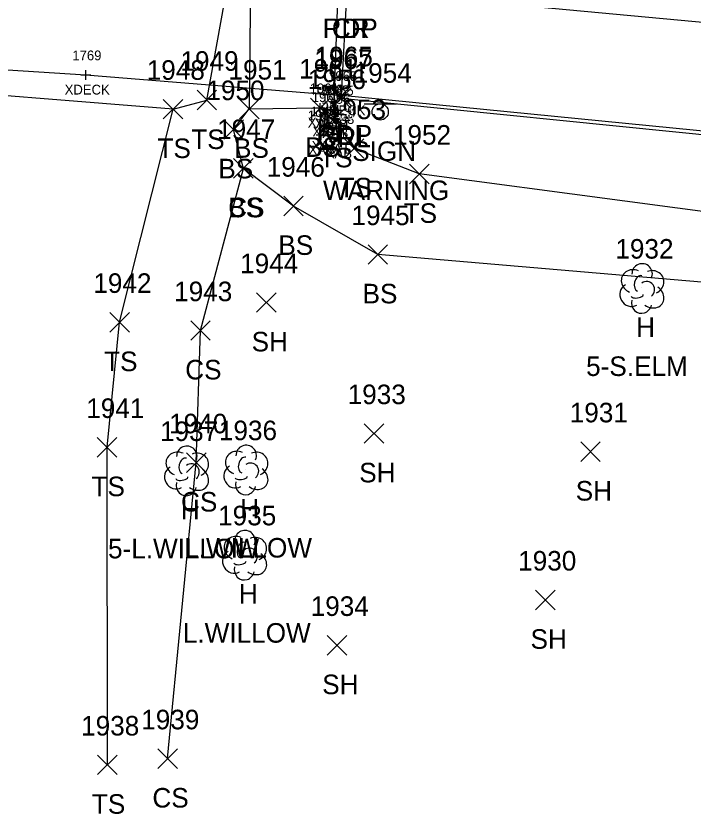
# Model space of a CAD drawing. Extents: x 1497084 to 1499861, y 734741 to 735567.
# Drawn here: x 1499561.5 to 1499630.8, y 735374.5 to 735456.1 of the extents above; entities that cross this region are included whole.
import ezdxf

# ---------------------------------------------------------------- set-up
doc = ezdxf.new("R2010")
doc.units = 0
for name, color, linetype in [('B_A', 7, 'Continuous'), ('B_I', 7, 'Continuous'), ('B_TIC', 7, 'Continuous'), ('BELB', 7, 'Continuous'), ('BSUBM', 7, 'Continuous'), ('L_A', 7, 'Continuous'), ('L_C', 7, 'Continuous'), ('L_I', 7, 'Continuous'), ('L_TIC', 7, 'Continuous'), ('LELB', 7, 'Continuous'), ('LTD', 7, 'Continuous'), ('P_A', 7, 'Continuous'), ('P_I', 7, 'Continuous'), ('P_TIC', 7, 'Continuous'), ('PET', 7, 'Continuous'), ('PRC', 7, 'Continuous'), ('R_A', 7, 'Continuous'), ('R_I', 7, 'Continuous'), ('R_TIC', 7, 'Continuous'), ('RGR', 7, 'Continuous'), ('S_A', 7, 'Continuous'), ('S_C', 7, 'Continuous'), ('S_I', 7, 'Continuous'), ('SSGN', 7, 'Continuous')]:
    doc.layers.add(name, color=color, linetype=linetype)

msp = doc.modelspace()

# ---------------------------------------------------------------- linework, layer by layer
at = {"layer": 'B_TIC'}
for p, q in [((1499568.694, 735450.037), (1499568.77, 735450.037)), ((1499594.852, 735447.923), (1499594.928, 735447.923)), ((1499592.69, 735446.665), (1499592.766, 735446.665)), ((1499593.42, 735446.544), (1499593.495, 735446.544)), ((1499593.42, 735446.544), (1499593.495, 735446.544)), ((1499594.057, 735446.482), (1499594.133, 735446.482)), ((1499594.478, 735446.445), (1499594.553, 735446.445)), ((1499594.478, 735446.445), (1499594.553, 735446.445)), ((1499593.182, 735445.765), (1499593.258, 735445.765)), ((1499594.16, 735445.59), (1499594.236, 735445.59)), ((1499594.16, 735445.59), (1499594.236, 735445.59)), ((1499592.764, 735443.901), (1499592.839, 735443.901)), ((1499593.093, 735444.295), (1499593.169, 735444.295)), ((1499594.415, 735443.992), (1499594.49, 735443.992)), ((1499594.536, 735443.527), (1499594.611, 735443.527))]:
    msp.add_line(p, q, dxfattribs=at)
for points in [[(1499568.691, 735449.537), (1499568.691, 735450.537)], [(1499568.191, 735450.037), (1499569.191, 735450.037)], [(1499594.349, 735447.923), (1499595.349, 735447.923)], [(1499594.849, 735447.423), (1499594.849, 735448.423)], [(1499592.687, 735446.165), (1499592.687, 735447.165)], [(1499593.416, 735446.044), (1499593.416, 735447.044)], [(1499593.416, 735446.044), (1499593.416, 735447.044)], [(1499594.054, 735445.982), (1499594.054, 735446.982)], [(1499592.187, 735446.665), (1499593.187, 735446.665)], [(1499592.916, 735446.544), (1499593.916, 735446.544)], [(1499592.916, 735446.544), (1499593.916, 735446.544)], [(1499593.179, 735445.265), (1499593.179, 735446.265)], [(1499593.554, 735446.482), (1499594.554, 735446.482)], [(1499593.974, 735446.445), (1499594.974, 735446.445)], [(1499593.974, 735446.445), (1499594.974, 735446.445)], [(1499594.474, 735445.945), (1499594.474, 735446.945)], [(1499594.474, 735445.945), (1499594.474, 735446.945)], [(1499592.679, 735445.765), (1499593.679, 735445.765)], [(1499593.657, 735445.59), (1499594.657, 735445.59)], [(1499593.657, 735445.59), (1499594.657, 735445.59)], [(1499594.157, 735445.09), (1499594.157, 735446.09)], [(1499594.157, 735445.09), (1499594.157, 735446.09)], [(1499593.09, 735443.795), (1499593.09, 735444.795)], [(1499592.26, 735443.901), (1499593.26, 735443.901)], [(1499592.59, 735444.295), (1499593.59, 735444.295)], [(1499592.76, 735443.401), (1499592.76, 735444.401)], [(1499593.911, 735443.992), (1499594.911, 735443.992)], [(1499594.411, 735443.492), (1499594.411, 735444.492)], [(1499594.532, 735443.027), (1499594.532, 735444.027)], [(1499594.032, 735443.527), (1499595.032, 735443.527)]]:
    msp.add_lwpolyline(points, dxfattribs=at)
at = {"layer": 'BELB'}
msp.add_lwpolyline([(1499512.442, 735453.405), (1499545.67, 735451.499), (1499568.691, 735450.037), (1499594.849, 735447.923)], dxfattribs=at)
at = {"layer": 'BSUBM'}
for points in [[(1499594.157, 735445.59), (1499594.532, 735443.527), (1499592.76, 735443.901), (1499592.687, 735446.665), (1499594.054, 735446.482), (1499594.992, 735471.577), (1499594.969, 735472.536), (1499595.34, 735473.493)], [(1499594.474, 735446.445), (1499594.157, 735445.59), (1499594.411, 735443.992), (1499593.09, 735444.295), (1499593.179, 735445.765), (1499593.416, 735446.544)], [(1499594.474, 735446.445), (1499593.416, 735446.544)]]:
    msp.add_lwpolyline(points, dxfattribs=at)
at = {"layer": 'L_TIC'}
for points in [[(1499580.073, 735446.466), (1499582.073, 735448.466)], [(1499582.073, 735446.466), (1499580.073, 735448.466)], [(1499576.616, 735445.541), (1499578.616, 735447.541)], [(1499578.616, 735445.541), (1499576.616, 735447.541)], [(1499584.417, 735445.564), (1499586.417, 735447.564)], [(1499586.417, 735445.564), (1499584.417, 735447.564)], [(1499591.687, 735445.665), (1499593.687, 735447.665)], [(1499593.687, 735445.665), (1499591.687, 735447.665)], [(1499593.157, 735444.59), (1499595.157, 735446.59)], [(1499595.157, 735444.59), (1499593.157, 735446.59)], [(1499582.811, 735443.464), (1499584.811, 735445.464)], [(1499584.811, 735443.464), (1499582.811, 735445.464)], [(1499595.152, 735441.523), (1499597.152, 735443.523)], [(1499597.152, 735441.523), (1499595.152, 735443.523)], [(1499583.819, 735439.486), (1499585.819, 735441.486)], [(1499585.819, 735439.486), (1499583.819, 735441.486)], [(1499583.819, 735439.486), (1499585.819, 735441.486)], [(1499585.819, 735439.486), (1499583.819, 735441.486)], [(1499601.806, 735438.913), (1499603.806, 735440.913)], [(1499603.806, 735438.913), (1499601.806, 735440.913)], [(1499588.947, 735435.639), (1499590.947, 735437.639)], [(1499590.947, 735435.639), (1499588.947, 735437.639)], [(1499597.567, 735430.683), (1499599.567, 735432.683)], [(1499599.567, 735430.683), (1499597.567, 735432.683)], [(1499586.171, 735425.771), (1499588.171, 735427.771)], [(1499588.171, 735425.771), (1499586.171, 735427.771)], [(1499571.156, 735423.754), (1499573.156, 735425.754)], [(1499573.156, 735423.754), (1499571.156, 735425.754)], [(1499579.424, 735422.906), (1499581.424, 735424.906)], [(1499581.424, 735422.906), (1499579.424, 735424.906)], [(1499597.177, 735412.38), (1499599.177, 735414.38)], [(1499599.177, 735412.38), (1499597.177, 735414.38)], [(1499569.867, 735410.967), (1499571.867, 735412.967)], [(1499571.867, 735410.967), (1499569.867, 735412.967)], [(1499619.329, 735410.52), (1499621.329, 735412.52)], [(1499621.329, 735410.52), (1499619.329, 735412.52)], [(1499578.995, 735409.397), (1499580.995, 735411.397)], [(1499580.995, 735409.397), (1499578.995, 735411.397)], [(1499614.705, 735395.365), (1499616.705, 735397.365)], [(1499616.705, 735395.365), (1499614.705, 735397.365)], [(1499593.392, 735390.725), (1499595.392, 735392.725)], [(1499595.392, 735390.725), (1499593.392, 735392.725)], [(1499576.065, 735379.133), (1499578.065, 735381.133)], [(1499578.065, 735379.133), (1499576.065, 735381.133)], [(1499569.905, 735378.498), (1499571.905, 735380.498)], [(1499571.905, 735378.498), (1499569.905, 735380.498)]]:
    msp.add_lwpolyline(points, dxfattribs=at)
at = {"layer": 'LELB'}
for points in [[(1499570.905, 735379.498), (1499570.867, 735411.967), (1499572.156, 735424.754), (1499577.616, 735446.541), (1499581.073, 735447.466), (1499585.691, 735473.006), (1499585.162, 735474.769), (1499583.013, 735483.125), (1499591.936, 735509.31), (1499594.485, 735538.631)], [(1499585.691, 735473.006), (1499585.417, 735446.564)], [(1499577.616, 735446.541), (1499518.061, 735451.305)], [(1499839.852, 735392.857), (1499780.55, 735401.529), (1499747.755, 735409.877), (1499711.761, 735420.596), (1499681.472, 735424.656), (1499665.959, 735425.746), (1499648.825, 735427.399), (1499598.567, 735431.683), (1499589.947, 735436.639), (1499584.819, 735440.486), (1499583.811, 735444.464), (1499585.417, 735446.564), (1499592.687, 735446.665)], [(1499841.233, 735396.637), (1499780.79, 735407.691), (1499746.046, 735413.364), (1499713.068, 735424.394), (1499683.252, 735430.826), (1499665.304, 735431.611), (1499657.007, 735431.775), (1499644.886, 735434.347), (1499602.806, 735439.913), (1499596.152, 735442.523), (1499594.157, 735445.59)], [(1499577.065, 735380.133), (1499579.995, 735410.397), (1499580.424, 735423.906), (1499584.819, 735440.486)]]:
    msp.add_lwpolyline(points, dxfattribs=at)
at = {"layer": 'LTD'}
for p, q in [((1499625.565, 735428.259), (1499625.565, 735428.259)), ((1499625.565, 735428.259), (1499625.565, 735428.259)), ((1499578.981, 735409.61), (1499578.981, 735409.61)), ((1499578.981, 735409.61), (1499578.981, 735409.61)), ((1499585.057, 735409.693), (1499585.057, 735409.693)), ((1499585.057, 735409.693), (1499585.057, 735409.693)), ((1499584.923, 735400.99), (1499584.923, 735400.99)), ((1499584.923, 735400.99), (1499584.923, 735400.99))]:
    msp.add_line(p, q, dxfattribs=at)
for centre in [(1499625.612, 735429.693), (1499579.028, 735411.044), (1499585.104, 735411.127), (1499584.97, 735402.424)]:
    msp.add_arc(centre, 1.047, 335.52715, 180.95627, dxfattribs=at)
for centre, major_axis, ratio, start_param, end_param in [((1499624.774, 735428.925), (1.21, -0.512), 0.895232, 1.570796, 4.712389), ((1499626.607, 735428.842), (-1.141, -0.483), 0.949671, 1.570796, 4.712389), ((1499625.357, 735428.717), (-0.208, -0.792), 0.645439, 3.141593, 6.283185), ((1499626.065, 735428.092), (-0.5, 0.667), 0.989748, 3.141593, 6.283185), ((1499624.482, 735427.55), (0.584, -1.042), 0.959034, 3.141593, 6.283185), ((1499626.565, 735427.426), (-1.09, 0.792), 0.841452, 1.570796, 4.712389), ((1499625.107, 735427.509), (-0.625, -0.083), 0.423636, 0, 3.141593), ((1499625.566, 735426.759), (0.265, 1.061), 0.942809, 1.570796, 4.712389), ((1499578.189, 735410.276), (1.21, -0.512), 0.895232, 1.570796, 4.712389), ((1499580.023, 735410.193), (-1.141, -0.483), 0.949671, 1.570796, 4.712389), ((1499584.265, 735410.36), (1.21, -0.512), 0.895232, 1.570796, 4.712389), ((1499586.099, 735410.277), (-1.141, -0.483), 0.949671, 1.570796, 4.712389), ((1499578.773, 735410.068), (-0.208, -0.792), 0.645439, 3.141593, 6.283185), ((1499579.481, 735409.443), (-0.5, 0.667), 0.989748, 3.141593, 6.283185), ((1499584.849, 735410.152), (-0.208, -0.792), 0.645439, 3.141593, 6.283185), ((1499585.557, 735409.527), (-0.5, 0.667), 0.989748, 3.141593, 6.283185), ((1499577.898, 735408.901), (0.584, -1.042), 0.959034, 3.141593, 6.283185), ((1499579.981, 735408.777), (-1.09, 0.792), 0.841452, 1.570796, 4.712389), ((1499583.974, 735408.985), (0.584, -1.042), 0.959034, 3.141593, 6.283185), ((1499586.057, 735408.86), (-1.09, 0.792), 0.841452, 1.570796, 4.712389), ((1499578.523, 735408.86), (-0.625, -0.083), 0.423636, 0, 3.141593), ((1499584.599, 735408.943), (-0.625, -0.083), 0.423636, 0, 3.141593), ((1499578.981, 735408.11), (0.265, 1.061), 0.942809, 1.570796, 4.712389), ((1499585.057, 735408.193), (0.265, 1.061), 0.942809, 1.570796, 4.712389), ((1499584.131, 735401.656), (1.21, -0.512), 0.895232, 1.570796, 4.712389), ((1499585.965, 735401.573), (-1.141, -0.483), 0.949671, 1.570796, 4.712389), ((1499584.715, 735401.448), (-0.208, -0.792), 0.645439, 3.141593, 6.283185), ((1499583.84, 735400.281), (0.584, -1.042), 0.959034, 3.141593, 6.283185), ((1499585.423, 735400.823), (-0.5, 0.667), 0.989748, 3.141593, 6.283185), ((1499585.923, 735400.157), (-1.09, 0.792), 0.841452, 1.570796, 4.712389), ((1499584.923, 735399.49), (0.265, 1.061), 0.942809, 1.570796, 4.712389), ((1499584.465, 735400.24), (-0.625, -0.083), 0.423636, 0, 3.141593)]:
    msp.add_ellipse(centre, major_axis=major_axis, ratio=ratio, start_param=start_param, end_param=end_param, dxfattribs=at)
at = {"layer": 'P_TIC'}
for points in [[(1499593.849, 735446.923), (1499595.849, 735448.923)], [(1499595.849, 735446.923), (1499593.849, 735448.923)]]:
    msp.add_lwpolyline(points, dxfattribs=at)
at = {"layer": 'PET'}
msp.add_lwpolyline([(1499842.353, 735402.928), (1499782.679, 735418.081), (1499750.409, 735424.994), (1499714.978, 735432.412), (1499683.044, 735438.059), (1499645.695, 735442.942), (1499594.849, 735447.923), (1499595.43, 735458.808), (1499596.077, 735469.991)], dxfattribs=at)
at = {"layer": 'PRC'}
msp.add_lwpolyline([(1499843.886, 735414.074), (1499783.911, 735429.159), (1499752.36, 735435.285), (1499717.649, 735442.891), (1499685.251, 735447.999), (1499648.687, 735453.839), (1499595.43, 735458.808)], dxfattribs=at)
at = {"layer": 'R_TIC'}
for points in [[(1499593.812, 735446.642), (1499595.812, 735448.642)], [(1499595.812, 735446.642), (1499593.812, 735448.642)]]:
    msp.add_lwpolyline(points, dxfattribs=at)
at = {"layer": 'RGR'}
msp.add_lwpolyline([(1499658.467, 735437.672), (1499645.798, 735441.95), (1499634.15, 735443.674), (1499594.812, 735447.642)], dxfattribs=at)
at = {"layer": 'SSGN'}
for p, q in [((1499597.163, 735447.097), (1499600.496, 735447.097)), ((1499598.81, 735446.264), (1499598.81, 735446.264))]:
    msp.add_line(p, q, dxfattribs=at)
msp.add_circle((1499598.81, 735446.264), 0.833, dxfattribs=at)

# ---------------------------------------------------------------- texts
at = {"layer": 'B_A'}
for s, p in [('XDECK', (1499566.533, 735448.037)), ('XDECK', (1499592.691, 735445.923)), ('XAB', (1499591.407, 735444.665)), ('XAT', (1499592.121, 735444.544)), ('XAT', (1499592.121, 735444.544)), ('XAB', (1499592.774, 735444.482)), ('XAT', (1499593.179, 735444.445)), ('XAT', (1499593.179, 735444.445)), ('XAT', (1499591.884, 735443.765)), ('XAT', (1499592.861, 735443.59)), ('XAB', (1499592.877, 735443.59)), ('XAB', (1499591.481, 735441.901)), ('XAT', (1499591.795, 735442.295)), ('XAT', (1499593.116, 735441.992)), ('XAB', (1499593.253, 735441.527))]:
    msp.add_text(s, height=1, dxfattribs=at).set_placement(p)
at = {"layer": 'B_I'}
for s, p in [('1769', (1499567.317, 735451.537)), ('1965', (1499593.479, 735449.423)), ('1961', (1499591.6, 735448.165)), ('1964', (1499592.046, 735448.044)), ('1964', (1499592.046, 735448.044)), ('1962', (1499592.684, 735447.982)), ('1955', (1499593.128, 735447.945)), ('1955', (1499593.128, 735447.945)), ('1963', (1499591.809, 735447.265)), ('1956', (1499592.783, 735447.09)), ('1956', (1499592.783, 735447.09)), ('1959', (1499591.41, 735445.401)), ('1960', (1499591.677, 735445.795)), ('1957', (1499593.065, 735445.492)), ('1958', (1499593.186, 735445.027))]:
    msp.add_text(s, height=1, dxfattribs=at).set_placement(p)
at = {"layer": 'L_A'}
for s, p in [('TS', (1499579.483, 735442.466)), ('BS', (1499591.128, 735441.665)), ('TS', (1499576.026, 735441.541)), ('BS', (1499583.858, 735441.564)), ('TS', (1499592.566, 735440.59)), ('BS', (1499582.252, 735439.464)), ('TS', (1499594.562, 735437.523)), ('CS', (1499583.26, 735435.486)), ('BS', (1499583.26, 735435.486)), ('TS', (1499601.215, 735434.913)), ('BS', (1499588.388, 735431.639)), ('BS', (1499597.008, 735426.683)), ('H', (1499624.998, 735423.259)), ('SH', (1499585.66, 735421.771)), ('TS', (1499570.565, 735419.754)), ('CS', (1499578.865, 735418.906)), ('SH', (1499596.665, 735408.38)), ('TS', (1499569.276, 735406.967)), ('SH', (1499618.817, 735406.52)), ('CS', (1499578.436, 735405.397)), ('H', (1499578.414, 735404.61)), ('H', (1499584.49, 735404.693)), ('H', (1499584.356, 735395.99)), ('SH', (1499614.193, 735391.365)), ('SH', (1499592.881, 735386.725)), ('CS', (1499575.506, 735375.133)), ('TS', (1499569.315, 735374.498))]:
    msp.add_text(s, height=2, dxfattribs=at).set_placement(p)
at = {"layer": 'L_C'}
for s, p in [('5-S.ELM', (1499619.88, 735419.259)), ('5-L.WILLOW', (1499570.965, 735400.61)), ('L.WILLOW', (1499578.758, 735400.693)), ('L.WILLOW', (1499578.624, 735391.99))]:
    msp.add_text(s, height=2, dxfattribs=at).set_placement(p)
at = {"layer": 'L_I'}
for s, p in [('1949', (1499578.373, 735450.466)), ('1948', (1499574.923, 735449.541)), ('1951', (1499583.291, 735449.564)), ('1961', (1499590.513, 735449.665)), ('1956', (1499591.409, 735448.59)), ('1950', (1499581.031, 735447.464)), ('1953', (1499593.459, 735445.523)), ('1947', (1499582.126, 735443.486)), ('1947', (1499582.126, 735443.486)), ('1952', (1499600.113, 735442.913)), ('1946', (1499587.199, 735439.639)), ('1945', (1499595.874, 735434.683)), ('1932', (1499622.872, 735431.259)), ('1944', (1499584.479, 735429.771)), ('1942', (1499569.463, 735427.754)), ('1943', (1499577.731, 735426.906)), ('1933', (1499595.484, 735416.38)), ('1941', (1499568.741, 735414.967)), ('1931', (1499618.203, 735414.52)), ('1940', (1499577.216, 735413.397)), ('1937', (1499576.288, 735412.61)), ('1936', (1499582.309, 735412.693)), ('1935', (1499582.23, 735403.99)), ('1930', (1499612.926, 735399.365)), ('1934', (1499591.7, 735394.725)), ('1939', (1499574.364, 735383.133)), ('1938', (1499568.212, 735382.498))]:
    msp.add_text(s, height=2, dxfattribs=at).set_placement(p)
at = {"layer": 'P_A'}
for s, p in [('RDP', (1499592.919, 735453.808)), ('CR', (1499593.864, 735453.808)), ('RDP', (1499592.337, 735442.923))]:
    msp.add_text(s, height=2, dxfattribs=at).set_placement(p)
at = {"layer": 'P_I'}
msp.add_text('1965', height=2, dxfattribs=at).set_placement((1499592.109, 735450.923))
at = {"layer": 'R_A'}
msp.add_text('GRL', height=2, dxfattribs=at).set_placement((1499592.356, 735442.642))
at = {"layer": 'R_I'}
msp.add_text('1967', height=2, dxfattribs=at).set_placement((1499592.072, 735450.642))
at = {"layer": 'S_A'}
msp.add_text('SIGN', height=2, dxfattribs=at).set_placement((1499595.948, 735441.243))
at = {"layer": 'S_C'}
msp.add_text('WARNING', height=2, dxfattribs=at).set_placement((1499592.956, 735437.243))
at = {"layer": 'S_I'}
msp.add_text('1954', height=2, dxfattribs=at).set_placement((1499596.097, 735449.243))

doc.saveas('drawing.dxf')
